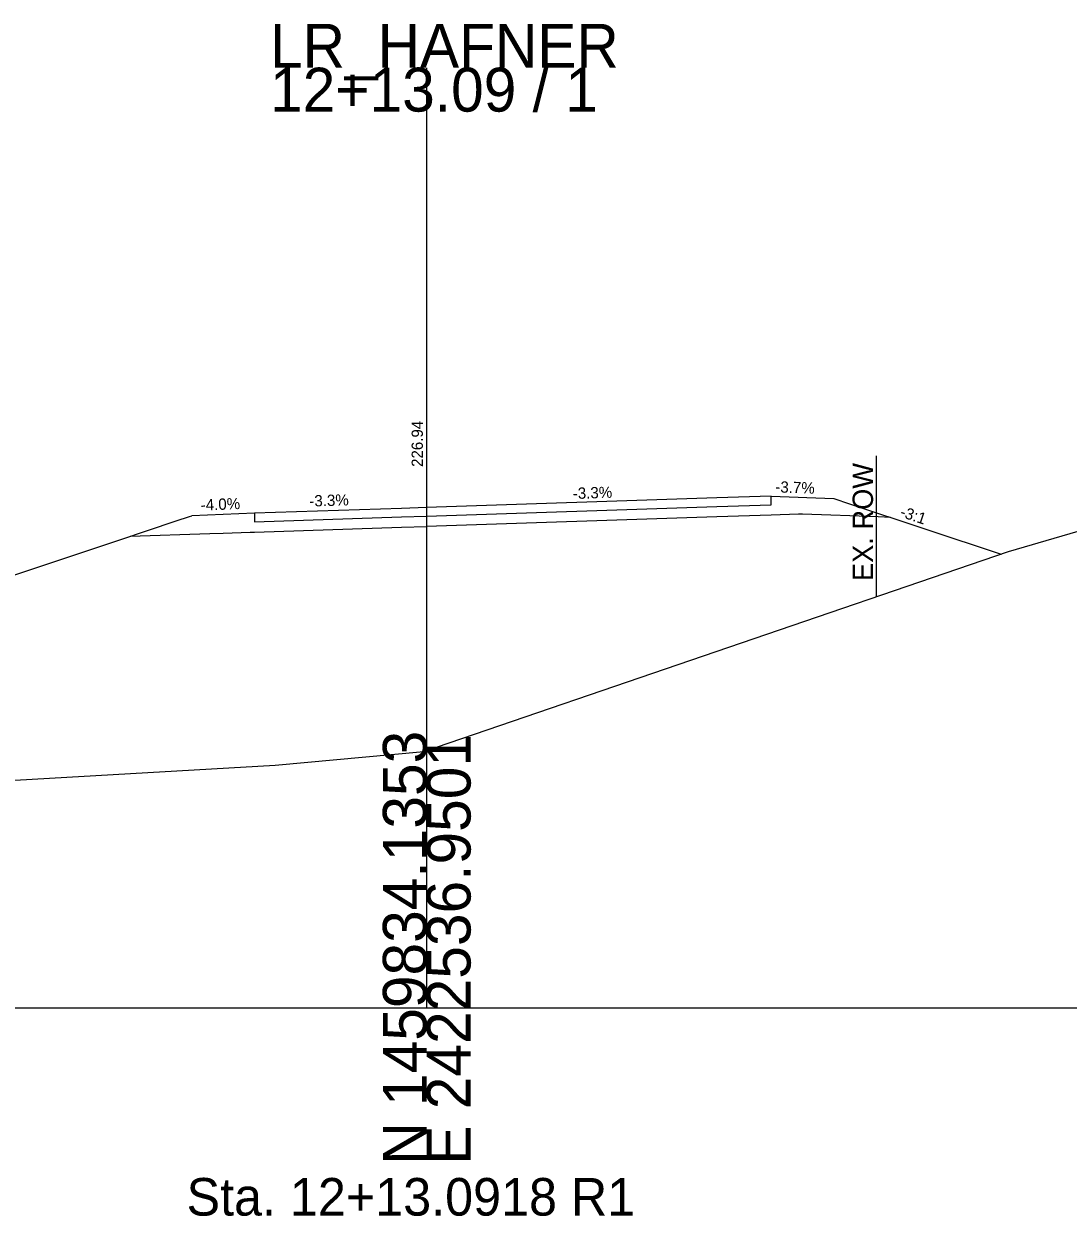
# Model space of a CAD drawing. Extents: x -26 to 403, y -13 to 3053.
# Drawn here: x 174.3 to 240.9, y 1986.7 to 2062.8 of the extents above; entities that cross this region are included whole.
import ezdxf

# ---------------------------------------------------------------- set-up
doc = ezdxf.new("R2010")
doc.units = 0
for name, color, linetype in [('CONST_DCH', 7, 'Continuous'), ('Draft_XS_Text', 7, 'Continuous'), ('DTM_CORRIDOR', 7, 'Continuous'), ('DTM_TEMP_DROP', 7, 'Continuous'), ('DTM_X_GROUND', 7, 'Continuous'), ('X_ROW', 7, 'Continuous'), ('X_ROW_TX', 7, 'Continuous'), ('XS_CELL', 7, 'Continuous'), ('XS_P_ASPHALT', 7, 'Continuous'), ('XS_P_GROUND', 7, 'Continuous'), ('XS_P_SHOULDER', 7, 'Continuous'), ('XS_P_SUBGRADE_GRANULAR', 7, 'Continuous'), ('XS_P_TX_CLEARZONE', 7, 'Continuous'), ('XS_P_TX_FS_BS', 7, 'Continuous')]:
    doc.layers.add(name, color=color, linetype=linetype)

msp = doc.modelspace()

# ---------------------------------------------------------------- linework, layer by layer
at = {"layer": 'DTM_X_GROUND'}
msp.add_lwpolyline([(0, 2014.222), (4.208, 2014.642), (15.672, 2014.982), (21.435, 2015.091), (25.668, 2015.25), (26.346, 2015.301), (37.524, 2015.147), (63.991, 2015.296), (73.583, 2014.978), (111.287, 2013.176), (127.983, 2013.527), (153.99, 2013.588), (156.335, 2013.544), (190.33, 2015.488), (199.812, 2016.364), (237.136, 2029.135), (246.894, 2031.975)], dxfattribs=at)
at = {"layer": 'X_ROW'}
msp.add_line((228.686, 2035.244), (228.686, 2026.244), dxfattribs=at)
at = {"layer": 'XS_CELL'}
for p, q in [((200, 2000), (200, 2060)), ((0, 2000), (200, 2000)), ((200, 2000), (400, 2000))]:
    msp.add_line(p, q, dxfattribs=at)
at = {"layer": 'XS_P_ASPHALT'}
msp.add_lwpolyline([(198.38, 2031.881), (188.998, 2031.57), (188.998, 2031.498), (188.998, 2031.028), (198.38, 2031.339), (199.997, 2031.391), (218.529, 2032.004), (221.997, 2032.115), (221.997, 2032.585), (221.997, 2032.657), (218.529, 2032.545), (199.997, 2031.932), (198.38, 2031.881)], dxfattribs=at)
at = {"layer": 'XS_P_GROUND'}
for points in [[(225.996, 2032.509), (226.996, 2032.175), (236.658, 2028.955)], [(131.377, 2013.535), (157.699, 2022.312), (159.289, 2022.841), (160.537, 2023.257), (160.733, 2023.322), (161.807, 2023.68), (161.975, 2023.736), (180.406, 2029.881), (183.998, 2031.077), (184.863, 2031.365), (184.998, 2031.41)]]:
    msp.add_lwpolyline(points, dxfattribs=at)
at = {"layer": 'XS_P_SHOULDER'}
for points in [[(221.997, 2032.657), (225.996, 2032.509)], [(188.998, 2031.57), (184.998, 2031.41)]]:
    msp.add_lwpolyline(points, dxfattribs=at)
at = {"layer": 'XS_P_SUBGRADE_GRANULAR'}
for points in [[(221.997, 2031.449), (218.529, 2031.337), (199.997, 2030.724)], [(229.601, 2031.307), (228.826, 2031.336), (223.997, 2031.515), (223.727, 2031.506), (221.997, 2031.449)], [(188.998, 2030.362), (198.38, 2030.673), (199.997, 2030.724)], [(181.07, 2030.101), (186.162, 2030.269), (186.998, 2030.296), (188.726, 2030.353), (188.998, 2030.362)]]:
    msp.add_lwpolyline(points, dxfattribs=at)

# ---------------------------------------------------------------- texts
at = {"layer": 'CONST_DCH'}
for p in [(210.996, 2032.623), (221.993, 2032.651), (188.994, 2031.564), (199.993, 2031.926)]:
    msp.add_text('X', height=0.012, dxfattribs=at).set_placement(p)
at = {"layer": 'Draft_XS_Text'}
msp.add_text('Sta. 12+13.0918 R1', height=2.4, dxfattribs=at).set_placement((184.67, 1986.75))
at = {"layer": 'DTM_CORRIDOR'}
for p in [(183.994, 2031.071), (228.991, 2027.478)]:
    msp.add_text('X', height=0.012, dxfattribs=at).set_placement(p)
at = {"layer": 'DTM_TEMP_DROP'}
for p in [(225.993, 2032.503), (184.993, 2031.408), (184.993, 2031.408), (184.994, 2031.404)]:
    msp.add_text('X', height=0.012, dxfattribs=at).set_placement(p)
at = {"layer": 'X_ROW_TX'}
msp.add_text('EX. ROW', height=1.3, rotation=90, dxfattribs=at).set_placement((228.486, 2027.244))
at = {"layer": 'XS_CELL'}
for s, p in [('LR_HAFNER', (190, 2060)), ('12+13.09 / 1', (190, 2057.2))]:
    msp.add_text(s, height=2.8, dxfattribs=at).set_placement(p)
for s, p in [('N 1459834.1353', (200, 1990)), ('E 2422536.9501', (202.8, 1990))]:
    msp.add_text(s, height=2.8, rotation=90, dxfattribs=at).set_placement(p)
at = {"layer": 'XS_P_ASPHALT'}
msp.add_text('X', height=0.012, dxfattribs=at).set_placement((230.612, 2026.937))
at = {"layer": 'XS_P_GROUND'}
msp.add_text('X', height=0.012, dxfattribs=at).set_placement((230.612, 2026.937))
at = {"layer": 'XS_P_TX_CLEARZONE'}
msp.add_text('226.94', height=0.72, rotation=90, dxfattribs=at).set_placement((199.756, 2034.525))
at = {"layer": 'XS_P_TX_FS_BS'}
for s, rotation, p in [('-3.3%', 1.89515, (209.335, 2032.477)), ('-3.7%', 357.87752, (222.241, 2032.903)), ('-4.0%', 2.2907, (185.589, 2031.738)), ('-3.3%', 1.89619, (192.521, 2031.991)), ('-3:1', 341.56447, (230.162, 2031.367))]:
    msp.add_text(s, height=0.72, rotation=rotation, dxfattribs=at).set_placement(p)

doc.saveas('drawing.dxf')
